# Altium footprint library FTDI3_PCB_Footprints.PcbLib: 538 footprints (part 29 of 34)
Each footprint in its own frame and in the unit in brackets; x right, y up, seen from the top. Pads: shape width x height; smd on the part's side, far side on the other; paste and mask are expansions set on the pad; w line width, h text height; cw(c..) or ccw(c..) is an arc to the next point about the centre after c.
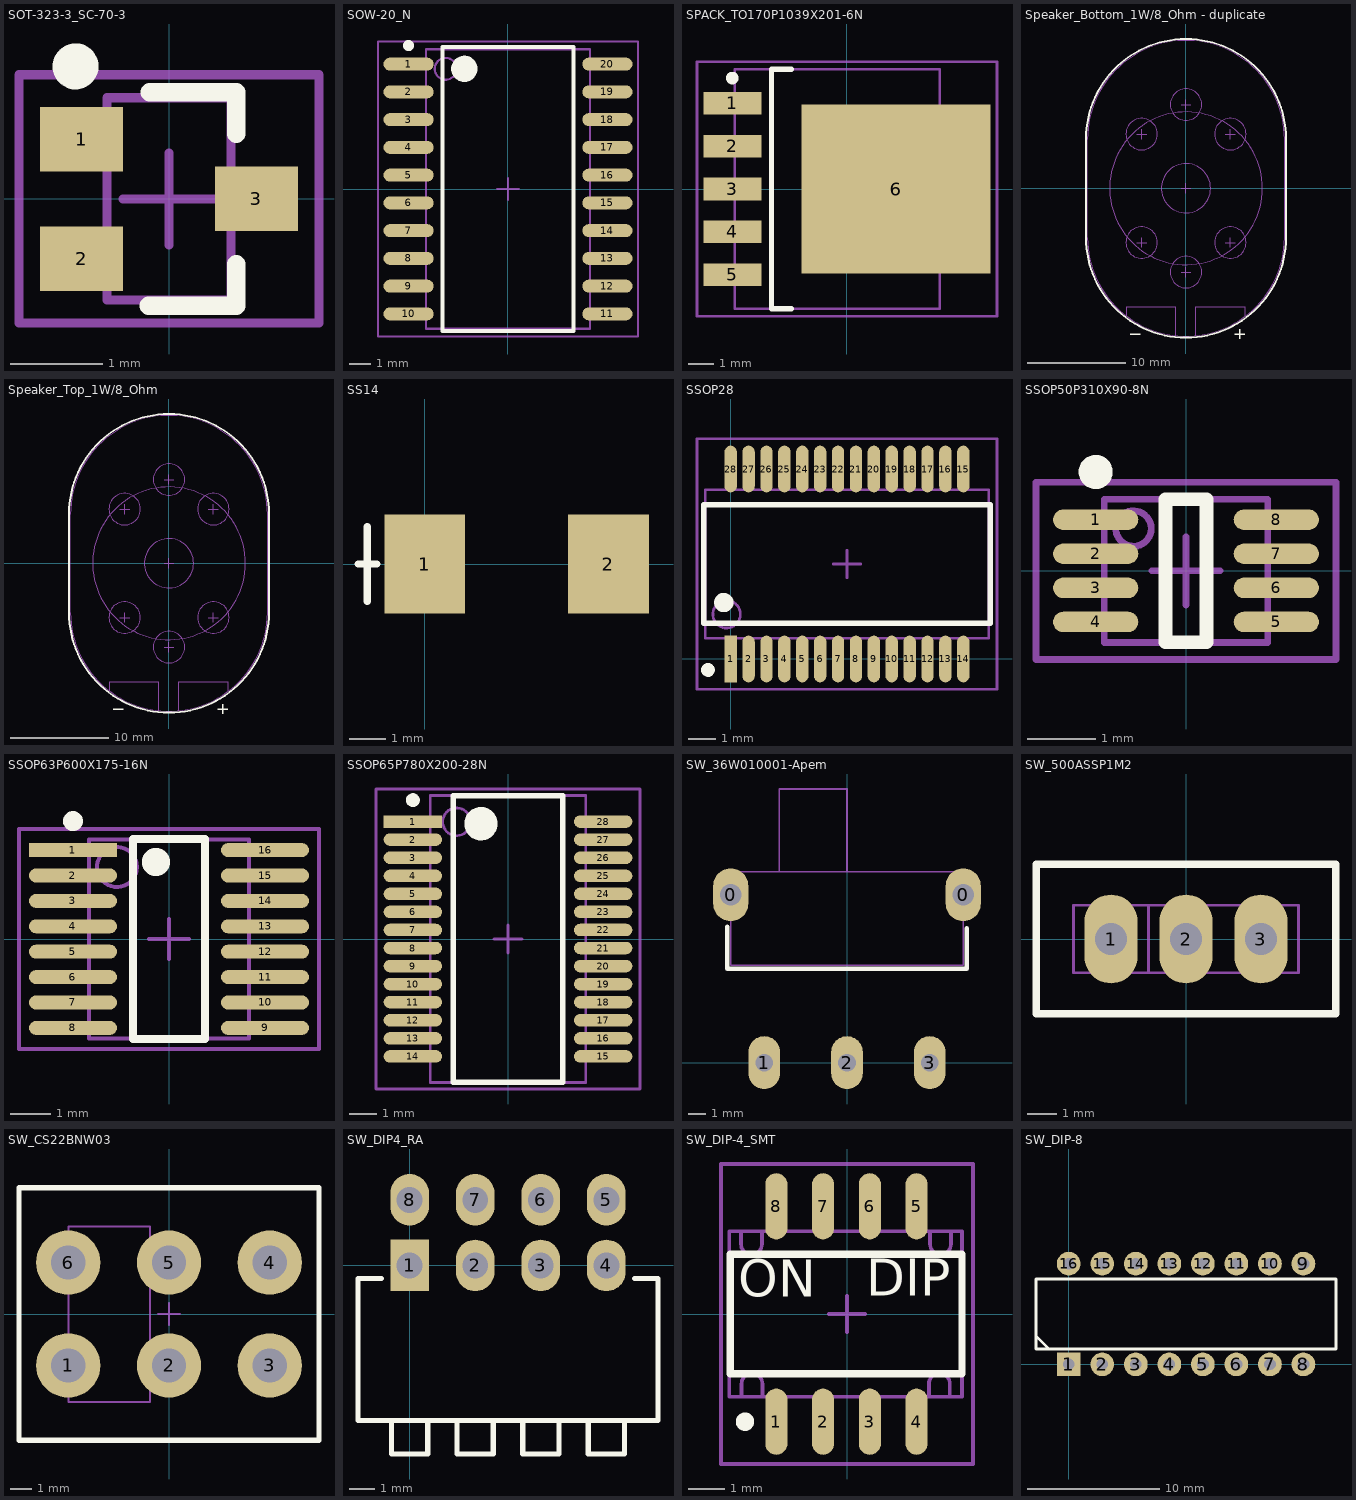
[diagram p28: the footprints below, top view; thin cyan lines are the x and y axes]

## SOT-323-3_SC-70-3 [mm] "SOT-323/SC-70, 3-Leads, Body 2.2x2.2mm (max), Pitch 0.65mm, IPC Medium Density"
height 1.1
pads (3):
  rect 0.9x0.7 smd: 1(-0.95,0.65) 2(-0.95,-0.65) 3(0.95,0)
Top Overlay:
  circle w0.25: c-1.015,1.44 r0.125
  lines w0.2: -0.22,-1.16 0.73,-1.16 0.73,-0.71 ; -0.21,1.16 0.73,1.16 0.73,0.71
M13_Assembly_Info:
  lines w0.1: -0.675,-1.1 -0.675,1.1 0.675,1.1 0.675,-1.1 -0.675,-1.1
M15_Country_Yard:
  lines w0.1: -0.5,0 0.5,0 ; 0,-0.5 0,0.5 ; -1.63,-1.35 -1.63,1.35 1.63,1.35 1.63,-1.35 -1.63,-1.35
3D body: height 1.1, standoff 0.1, extent -0.675,-1.1 0.675,1.1

## SOW-20_N [mm] "SOIC, 20-Leads, Body 12.8x7.5mm, Pitch 1.27mm, IPC Medium Density"
height 2.65
pads (20):
  oval 2.3x0.6 smd: 1(-4.55,5.715) 2(-4.55,4.445) 3(-4.55,3.175) 4(-4.55,1.905) 5(-4.55,0.635) 6(-4.55,-0.635) 7(-4.55,-1.905) 8(-4.55,-3.175) 9(-4.55,-4.445) 10(-4.55,-5.715) 11(4.55,-5.715) 12(4.55,-4.445) 13(4.55,-3.175) 14(4.55,-1.905) 15(4.55,-0.635) 16(4.55,0.635) 17(4.55,1.905) 18(4.55,3.175) 19(4.55,4.445) 20(4.55,5.715)
Top Overlay:
  circle w0.6: c-2,5.5 r0.3
  circle w0.25: c-4.55,6.565 r0.125
  lines w0.2: -3,-6.5 3,-6.5 3,6.5 -3,6.5 -3,-6.5
M13_Assembly_Info:
  circle w0.1: c-2.85,5.5 r0.5
  lines w0.1: -3.75,-6.4 3.75,-6.4 3.75,6.4 -3.75,6.4 -3.75,-6.4
M15_Country_Yard:
  lines w0.1: -0.5,0 0.5,0 ; 0,-0.5 0,0.5 ; -5.95,-6.75 5.95,-6.75 5.95,6.75 -5.95,6.75 -5.95,-6.75
3D body: height 2.65, standoff 0, extent -3.75,-6.4 3.75,6.4

## SPACK_TO170P1039X201-6N [mm] "S-PAK, 6-Pads, Body 8.1x9.5mm (max), IPC Medium Density"
height 2.01
pads (6):
  rect 2.3x0.9 smd: 1(-4.55,3.4) 2(-4.55,1.7) 3(-4.55,0) 4(-4.55,-1.7) 5(-4.55,-3.4)
  rect 7.5x6.7 smd: 6(1.95,0)
Top Overlay:
  circle w0.25: c-4.55,4.4 r0.125
  lines w0.2: -2.2,-4.75 -3,-4.75 -3,4.75 -2.2,4.75
M13_Assembly_Info:
  lines w0.1: -4.45,-4.75 3.68,-4.75 3.68,4.75 -4.45,4.75 -4.45,-4.75
M15_Country_Yard:
  lines w0.1: -0.5,0 0.5,0 ; 0,-0.5 0,0.5 ; -5.95,-5.05 5.95,-5.05 5.95,5.05 -5.95,5.05 -5.95,-5.05
3D body: height 2.01, standoff 0.13, extent -4.45,-4.75 3.68,4.75

## Speaker_Bottom_1W/8_Ohm - duplicate [mm] "Speaker; 1W; 8-Ohms; HONSON ACOUSTICS (SHENZHEN) CO., LTD; M3020N008041-R1206F-2"
height 2.65
Top Overlay:
  lines w0.127: -5.65,-14.79 -4.65,-14.79 ; 4.96,-14.79 5.96,-14.79 ; 5.46,-15.29 5.46,-14.29
  lines w0.2: -10.15,-5 ccw(c0,-5) 10.15,-5 10.15,5 ccw(c0,5) -10.15,5 -10.15,-5
M13_Assembly_Info:
  circle w0.1: c0,0 r7.75
  circle w0.1: c0,-8.5 r1.6
  circle w0.1: c4.5,-5.5 r1.6
  circle w0.1: c-4.5,-5.5 r1.6
  circle w0.1: c-4.5,5.5 r1.6
  circle w0.1: c4.5,5.5 r1.6
  circle w0.1: c0,8.5 r1.6
  circle w0.1: c0,0 r2.5
  lines w0.1: -6.03,-12.98 -6.03,-12 -1.03,-12 -1.03,-14.95 ; -5,-5.5 -4,-5.5 ; -5,5.5 -4,5.5 ; -4.5,-6 -4.5,-5 ; -4.5,5 -4.5,6 ; -0.5,-8.5 0.5,-8.5 ; -0.5,0 0.5,0 ; -0.5,8.5 0.5,8.5 ; 0,-9 0,-8 ; 0,-0.5 0,0.5 ; 0,8 0,9 ; 1,-14.95 1,-12 6,-12 6,-13 ; 4,-5.5 5,-5.5 ; 4,5.5 5,5.5 ; 4.5,-6 4.5,-5 ; 4.5,5 4.5,6 ; -10,-5 ccw(c0,-5) 10,-5 10,5 ccw(c0,5) -10,5 -10,-5
M15_Country_Yard:
  lines w0.1: -0.5,0 0.5,0 ; 0,-0.5 0,0.5
3D body: height 0, standoff -1.6, extent -7.689,-7.735 7.75,7.735
3D body: height -0.05, standoff -3.5, extent -9.35,-14.48 10.571,5.48
3D body: height -0.05, standoff -3.5, extent -9.921,-4.98 10,14.98
3D body: height 3.65, standoff -3.5, extent -10,-5 10,5

## Speaker_Top_1W/8_Ohm [mm] "Speaker; 1W; 8-Ohms; HONSON ACOUSTICS (SHENZHEN) CO., LTD; M3020N008041-R1206F-2"
height 2.65
Top Overlay:
  lines w0.127: -5.65,-14.79 -4.65,-14.79 ; 4.96,-14.79 5.96,-14.79 ; 5.46,-15.29 5.46,-14.29
  lines w0.2: -10.15,-5 ccw(c0,-5) 10.15,-5 10.15,5 ccw(c0,5) -10.15,5 -10.15,-5
M13_Assembly_Info:
  circle w0.1: c0,0 r2.5
  circle w0.1: c0,8.5 r1.6
  circle w0.1: c4.5,5.5 r1.6
  circle w0.1: c-4.5,5.5 r1.6
  circle w0.1: c-4.5,-5.5 r1.6
  circle w0.1: c4.5,-5.5 r1.6
  circle w0.1: c0,-8.5 r1.6
  circle w0.1: c0,0 r7.75
  lines w0.1: -6.03,-12.98 -6.03,-12 -1.03,-12 -1.03,-14.95 ; -5,-5.5 -4,-5.5 ; -5,5.5 -4,5.5 ; -4.5,-6 -4.5,-5 ; -4.5,5 -4.5,6 ; -0.5,-8.5 0.5,-8.5 ; -0.5,0 0.5,0 ; -0.5,8.5 0.5,8.5 ; 0,-9 0,-8 ; 0,-0.5 0,0.5 ; 0,8 0,9 ; 1,-14.95 1,-12 6,-12 6,-13 ; 4,-5.5 5,-5.5 ; 4,5.5 5,5.5 ; 4.5,-6 4.5,-5 ; 4.5,5 4.5,6 ; -10,-5 ccw(c0,-5) 10,-5 10,5 ccw(c0,5) -10,5 -10,-5
M15_Country_Yard:
  lines w0.1: -0.5,0 0.5,0 ; 0,-0.5 0,0.5
3D body: height 3.65, standoff 0.2, extent -10,-5 10,5
3D body: height 3.65, standoff 0.2, extent -9.921,-4.98 10,14.98
3D body: height 3.65, standoff 0.2, extent -9.921,-14.98 10,4.98
3D body: height 0, standoff -1.6, extent -7.689,-7.735 7.75,7.735

## SS14 [mm]
pads (2):
  rect 2.2x2.7 smd: 1(0,0) 2(5,0)
Top Overlay:
  lines w0.2: -1.818,0 -1.31,0 ; -1.564,-1.016 -1.564,1.016

## SSOP28 [mm] "SSOP; 28 Leads; Body Width 5.3 mm; Pitch 0.65 mm"
height 1.99
pads (28):
  rect 0.45x1.7 smd: 1(0,0)
  oval 0.45x1.7 smd: 2(0.65,0) 3(1.3,0) 4(1.95,0) 5(2.6,0) 6(3.25,0) 7(3.9,0) 8(4.55,0) 9(5.2,0) 10(5.85,0) 11(6.5,0) 12(7.15,0) 13(7.8,0) 14(8.45,0) 15(8.45,6.9) 16(7.8,6.9) 17(7.15,6.9) 18(6.5,6.9) 19(5.85,6.9) 20(5.2,6.9) 21(4.55,6.9) 22(3.9,6.9) 23(3.25,6.9) 24(2.6,6.9) 25(1.95,6.9) 26(1.3,6.9) 27(0.65,6.9) 28(0,6.9)
Top Overlay:
  circle w0.25: c-0.825,-0.4 r0.125
  circle w0.5: c-0.25,2.05 r0.1
  lines w0.2: -0.975,1.3 -0.975,5.6 9.425,5.6 9.425,1.3 -0.975,1.3
M13_Assembly_Info:
  circle w0.1: c-0.15,1.625 r0.5
  lines w0.1: -0.925,0.75 9.375,0.75 9.375,6.15 -0.925,6.15 -0.925,0.75
M15_Country_Yard:
  lines w0.1: 3.725,3.45 4.725,3.45 ; 4.225,2.95 4.225,3.95 ; -1.225,-1.1 9.675,-1.1 9.675,8 -1.225,8 -1.225,-1.1
3D body: height 0, standoff 0, extent -0.925,0.75 9.375,6.15

## SSOP50P310X90-8N [mm] "SSOP, 8-Leads, Body 2.1x2.4mm (max), Pitch 0.50mm, IPC Medium Density"
height 0.9
pads (8):
  oval 1.25x0.3 smd: 1(-1.325,0.75) 2(-1.325,0.25) 3(-1.325,-0.25) 4(-1.325,-0.75) 5(1.325,-0.75) 6(1.325,-0.25) 7(1.325,0.25) 8(1.325,0.75)
Top Overlay:
  circle w0.25: c-1.325,1.45 r0.125
  lines w0.2: -0.3,-1.05 -0.3,1.05 0.3,1.05 0.3,-1.05 -0.3,-1.05
M13_Assembly_Info:
  circle w0.1: c-0.77,0.62 r0.26
  lines w0.1: -1.2,-1.05 -1.2,1.05 1.2,1.05 1.2,-1.05 -1.2,-1.05
M15_Country_Yard:
  lines w0.1: -0.5,0 0.5,0 ; 0,-0.5 0,0.5 ; -2.2,-1.3 -2.2,1.3 2.2,1.3 2.2,-1.3 -2.2,-1.3
3D body: height 0.9, standoff 0.1, extent -1.2,-1.05 1.2,1.05

## SSOP63P600X175-16N [mm] "SOP, 16-Leads, Body 5.0x4.0mm (max), Pitch 0.63mm, IPC Medium Density"
height 1.75
pads (16):
  rect 2.2x0.35 smd: 1(-2.4,2.222)
  oval 2.2x0.35 smd: 2(-2.4,1.587) 3(-2.4,0.953) 4(-2.4,0.318) 5(-2.4,-0.318) 6(-2.4,-0.953) 7(-2.4,-1.587) 8(-2.4,-2.222) 9(2.4,-2.222) 10(2.4,-1.587) 11(2.4,-0.953) 12(2.4,-0.318) 13(2.4,0.318) 14(2.4,0.953) 15(2.4,1.587) 16(2.4,2.222)
Top Overlay:
  circle w0.6: c-0.325,1.925 r0.05
  circle w0.25: c-2.4,2.947 r0.125
  lines w0.2: -0.9,-2.5 0.9,-2.5 0.9,2.5 -0.9,2.5 -0.9,-2.5
M13_Assembly_Info:
  circle w0.1: c-1.3,1.8 r0.5
  lines w0.1: -1.995,-2.49 1.995,-2.49 1.995,2.49 -1.995,2.49 -1.995,-2.49
M15_Country_Yard:
  lines w0.1: -0.5,0 0.5,0 ; 0,-0.5 0,0.5 ; -3.75,-2.75 3.75,-2.75 3.75,2.75 -3.75,2.75 -3.75,-2.75
3D body: height 1.75, standoff 0.25, extent -1.995,-2.49 1.995,2.49

## SSOP65P780X200-28N [mm] "SSOP, 28-Leads, Body 10.3x5.6mm (max), Pitch 0.65mm, IPC Medium Density"
height 2
pads (28):
  rect 2.1x0.45 smd: 1(-3.425,4.225)
  oval 2.1x0.45 smd: 2(-3.425,3.575) 3(-3.425,2.925) 4(-3.425,2.275) 5(-3.425,1.625) 6(-3.425,0.975) 7(-3.425,0.325) 8(-3.425,-0.325) 9(-3.425,-0.975) 10(-3.425,-1.625) 11(-3.425,-2.275) 12(-3.425,-2.925) 13(-3.425,-3.575) 14(-3.425,-4.225) 15(3.425,-4.225) 16(3.425,-3.575) 17(3.425,-2.925) 18(3.425,-2.275) 19(3.425,-1.625) 20(3.425,-0.975) 21(3.425,-0.325) 22(3.425,0.325) 23(3.425,0.975) 24(3.425,1.625) 25(3.425,2.275) 26(3.425,2.925) 27(3.425,3.575) 28(3.425,4.225)
Top Overlay:
  circle w0.6: c-0.975,4.15 r0.3
  circle w0.25: c-3.425,5 r0.125
  lines w0.2: -1.975,-5.15 1.975,-5.15 1.975,5.15 -1.975,5.15 -1.975,-5.15
M13_Assembly_Info:
  circle w0.1: c-1.85,4.22 r0.5
  lines w0.1: -2.8,-5.17 2.8,-5.17 2.8,5.17 -2.8,5.17 -2.8,-5.17
M15_Country_Yard:
  lines w0.1: -0.5,0 0.5,0 ; 0,-0.5 0,0.5 ; -4.75,-5.4 4.75,-5.4 4.75,5.4 -4.75,5.4 -4.75,-5.4
3D body: height 2.02, standoff -0.13, extent -3.928,-5.18 3.828,5.15

## SW_36W010001-Apem [mm] "Minature Slide Switch; R/A SP-DT; Apem; 36W010001"
height 6.6
pads (5):
  oval 2x3 hole 1.2: 0(-6.6,9.53) 0(6.6,9.53)
  oval 1.8x3 hole 1: 1(-4.7,0) 2(0,0) 3(4.7,0)
Top Overlay:
  lines w0.254: -6.8,7.71 -6.8,5.33 6.8,5.33 6.8,7.63
M13_Assembly_Info:
  lines w0.1: -3.85,10.83 -3.85,15.53 0,15.53 0,10.83 ; -6.6,5.53 6.6,5.53 6.6,10.83 -6.6,10.83 -6.6,5.53
3D body: height 6.6, standoff 0, extent -6.6,5.53 6.6,10.83

## SW_500ASSP1M2 [mm] "500A series; Sub-Minature; Slide Switch;SP-DT; E-Switch"
height 10.94
pads (3):
  oval 1.8x3 hole 1.09: 1(-2.54,0) 2(0,0) 3(2.54,0)
Top Overlay:
  lines w0.254: -5.08,-2.54 -5.08,2.54 5.08,2.54 5.08,-2.54 -5.08,-2.54
M13_Assembly_Info:
  lines w0.1: -1.27,-1.143 3.81,-1.143 3.81,1.143 -1.27,1.143 ; -1.27,-1.143 -3.81,-1.143 -3.81,1.143 -1.27,1.143 ; -1.27,-1.143 -1.27,1.143 ; -5.08,-2.54 5.08,-2.54 5.08,2.54 -5.08,2.54 -5.08,-2.54
3D body: height 0, standoff 0, extent -5.08,-2.54 5.08,2.54

## SW_CS22BNW03 [mm] "Switch; DPDT; Minature; Power Rated; NKK Switches"
height 14.8
pads (6):
  round 3 hole 1.6: 1(-4.7,-2.4) 2(0,-2.4) 3(4.7,-2.4) 4(4.7,2.4) 5(0,2.4) 6(-4.7,2.4)
Top Overlay:
  lines w0.254: -7,-5.9 7,-5.9 7,5.9 -7,5.9 -7,-5.9
M13_Assembly_Info:
  lines w0.1: -7,-5.9 7,-5.9 7,5.9 -7,5.9 -7,-5.9 ; -4.69,-4.11 -0.89,-4.11 -0.89,4.09 -4.69,4.09 -4.69,-4.11
M15_Country_Yard:
  lines w0.1: -0.5,0 0.5,0 ; 0,-0.5 0,0.5
3D body: height 0, standoff 0, extent -7,-5.9 7,5.9

## SW_DIP4_RA [mm]
height 9.65
pads (8):
  rect 1.5x2 hole 1: 1(0,0)
  oval 1.5x2 hole 1: 2(2.54,0) 3(5.08,0) 4(7.62,0) 5(7.62,2.54) 6(5.08,2.54) 7(2.54,2.54) 8(0,2.54)
Top Overlay:
  lines w0.2: -1.103,-0.5 -2,-0.5 -2,-6 9.62,-6 9.62,-0.5 8.722,-0.5 ; -0.7,-6.003 -0.7,-7.302 0.7,-7.302 0.7,-6.003 ; 1.84,-6.003 1.84,-7.302 3.24,-7.302 3.24,-6.003 ; 4.38,-6.003 4.38,-7.302 5.78,-7.302 5.78,-6.003 ; 6.92,-6.003 6.92,-7.302 8.32,-7.302 8.32,-6.003
3D body: height 3.6, standoff 2, extent 6.92,-7.3 8.32,-6
3D body: height 3.6, standoff 2, extent 4.38,-7.3 5.78,-6
3D body: height 3.6, standoff 2, extent 1.84,-7.3 3.24,-6
3D body: height 3.6, standoff 2, extent -0.7,-7.3 0.7,-6
3D body: height 9.9, standoff 0, extent -2,-6 9.62,-0.5

## SW_DIP-4_SMT [mm] "DIP Switch; SMT"
height 1.5
pads (8):
  oval 0.6x1.8 smd: 1(-1.92,-2.925) 2(-0.65,-2.925) 3(0.62,-2.925) 4(1.89,-2.925) 5(1.89,2.925) 6(0.62,2.925) 7(-0.65,2.925) 8(-1.92,2.925)
Top Overlay:
  circle w0.25: c-2.77,-2.925 r0.125
  lines w0.2: -3.175,-1.625 3.125,-1.625 3.125,1.625 -3.175,1.625 -3.175,-1.625
  text "ON" at -2.952,0.466 h1
  text "DIP" at 0.525,0.5 h1
M13_Assembly_Info:
  lines w0.1: -2.879,2.249 -2.879,1.892 ccw(c-2.595,1.892) -2.311,1.892 -2.311,2.25 ; -2.866,-2.25 -2.866,-1.892 cw(c-2.582,-1.892) -2.298,-1.892 -2.298,-2.249 ; 2.226,-2.25 2.226,-1.892 cw(c2.51,-1.892) 2.794,-1.892 2.794,-2.25 ; 2.256,2.249 2.256,1.892 ccw(c2.54,1.892) 2.824,1.892 2.824,2.25 ; -3.2,-2.25 3.125,-2.25 3.125,2.25 -3.2,2.25 -3.2,-2.25
M15_Country_Yard:
  lines w0.1: -0.5,0 0.5,0 ; 0,-0.5 0,0.5 ; -3.425,-4.075 3.425,-4.075 3.425,4.075 -3.425,4.075 -3.425,-4.075
3D body: height 1.5, standoff 0.1, extent -3.2,-2.25 3.125,2.25

## SW_DIP-8 [mm] "Switch DIP; 8 way; 16 Leads; Row Spacing 7.62 mm; Pitch 2.54 mm"
height 5.08
pads (16):
  rect 1.8x1.8 hole 0.9: 1(0,0)
  round 1.8 hole 0.9: 2(2.54,0) 3(5.08,0) 4(7.62,0) 5(10.16,0) 6(12.7,0) 7(15.24,0) 8(17.78,0) 9(17.78,7.62) 10(15.24,7.62) 11(12.7,7.62) 12(10.16,7.62) 13(7.62,7.62) 14(5.08,7.62) 15(2.54,7.62) 16(0,7.62)
Top Overlay:
  lines w0.2: -2.48,2.15 -1.495,1.165 ; -2.48,1.16 20.25,1.16 20.25,6.46 -2.48,6.46 -2.48,1.16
